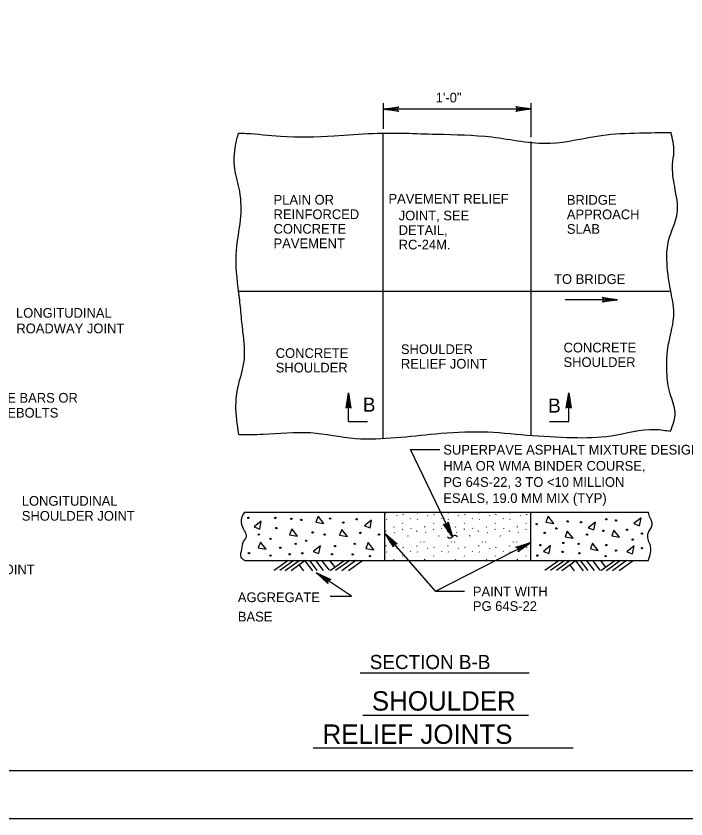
# Model space of a CAD drawing. Extents: x 638216 to 639962, y 297510 to 299292.
# Drawn here: x 638609.5 to 638817, y 297510.2 to 297758.8 of the extents above; entities that cross this region are included whole.
import ezdxf

# ---------------------------------------------------------------- set-up
doc = ezdxf.new("R2010")
doc.units = 0
for name, color, linetype in [('1', 7, 'Continuous'), ('2', 7, 'Continuous'), ('3', 7, 'Continuous'), ('PLT-BNDY', 7, 'Continuous')]:
    doc.layers.add(name, color=color, linetype=linetype)

msp = doc.modelspace()

# ---------------------------------------------------------------- linework, layer by layer
at = {"layer": '1'}
for p, q in [((638744.68, 297597.58), (638731.62, 297624.67)), ((638724.08, 297604.86), (638724.16, 297605.02)), ((638727.38, 297604.23), (638727.45, 297604.12)), ((638729.39, 297604.44), (638729.46, 297604.6)), ((638733.65, 297604.86), (638733.72, 297605.02)), ((638736.94, 297604.23), (638737.01, 297604.12)), ((638738.95, 297604.44), (638739.03, 297604.6)), ((638743.22, 297604.86), (638743.29, 297605.02)), ((638746.51, 297604.23), (638746.58, 297604.12)), ((638748.52, 297604.44), (638748.59, 297604.6)), ((638752.78, 297604.86), (638752.85, 297605.02)), ((638756.07, 297604.23), (638756.15, 297604.12)), ((638758.09, 297604.44), (638758.16, 297604.6)), ((638762.35, 297604.86), (638762.42, 297605.02)), ((638765.64, 297604.23), (638765.71, 297604.12)), ((638767.65, 297604.44), (638767.72, 297604.6)), ((638724.2, 297603.1), (638724.27, 297602.99)), ((638729.15, 297601.82), (638729.22, 297601.71)), ((638731.64, 297603.29), (638731.71, 297603.18)), ((638733.76, 297603.1), (638733.83, 297602.99)), ((638738.72, 297601.82), (638738.79, 297601.71)), ((638741.2, 297603.29), (638741.27, 297603.18)), ((638743.33, 297603.1), (638743.4, 297602.99)), ((638748.28, 297601.82), (638748.35, 297601.71)), ((638750.77, 297603.29), (638750.84, 297603.18)), ((638752.89, 297603.1), (638752.97, 297602.99)), ((638757.85, 297601.82), (638757.92, 297601.71)), ((638760.33, 297603.29), (638760.41, 297603.18)), ((638762.46, 297603.1), (638762.53, 297602.99)), ((638767.41, 297601.82), (638767.49, 297601.71)), ((638723.92, 297599.42), (638723.94, 297599.26)), ((638726.48, 297600.61), (638726.55, 297600.77)), ((638726.74, 297598.95), (638726.81, 297598.84)), ((638729.21, 297599.88), (638729.28, 297600.04)), ((638731.7, 297600.22), (638731.78, 297600.12)), ((638733.48, 297599.42), (638733.5, 297599.26)), ((638736.04, 297600.61), (638736.11, 297600.77)), ((638736.3, 297598.95), (638736.37, 297598.84)), ((638738.77, 297599.88), (638738.85, 297600.04)), ((638741.27, 297600.22), (638741.34, 297600.12)), ((638743.05, 297599.42), (638743.07, 297599.26)), ((638745.61, 297600.61), (638745.68, 297600.77)), ((638745.87, 297598.95), (638745.94, 297598.84)), ((638748.34, 297599.88), (638748.41, 297600.04)), ((638750.84, 297600.22), (638750.91, 297600.12)), ((638752.62, 297599.42), (638752.63, 297599.26)), ((638755.17, 297600.61), (638755.25, 297600.77)), ((638755.44, 297598.95), (638755.51, 297598.84)), ((638757.91, 297599.88), (638757.98, 297600.04)), ((638760.4, 297600.22), (638760.47, 297600.12)), ((638762.18, 297599.42), (638762.2, 297599.26)), ((638764.74, 297600.61), (638764.81, 297600.77)), ((638765, 297598.95), (638765.07, 297598.84)), ((638767.47, 297599.88), (638767.54, 297600.04)), ((638725.15, 297596.07), (638725.22, 297595.96)), ((638726.17, 297596.03), (638726.24, 297595.92)), ((638730.85, 297597.79), (638730.92, 297597.95)), ((638734.71, 297596.07), (638734.78, 297595.96)), ((638735.74, 297596.03), (638735.81, 297595.92)), ((638740.41, 297597.79), (638740.48, 297597.95)), ((638744.28, 297596.07), (638744.35, 297595.96)), ((638745.3, 297596.03), (638745.37, 297595.92)), ((638749.98, 297597.79), (638750.05, 297597.95)), ((638753.84, 297596.07), (638753.92, 297595.96)), ((638754.87, 297596.03), (638754.94, 297595.92)), ((638759.54, 297597.79), (638759.62, 297597.95)), ((638763.41, 297596.07), (638763.48, 297595.96)), ((638764.43, 297596.03), (638764.51, 297595.92)), ((638724.08, 297594.74), (638724.16, 297594.9)), ((638727.38, 297594.11), (638727.45, 297594.01)), ((638729.39, 297594.32), (638729.46, 297594.49)), ((638733.65, 297594.74), (638733.72, 297594.9)), ((638736.94, 297594.11), (638737.01, 297594.01)), ((638738.95, 297594.32), (638739.03, 297594.49)), ((638743.22, 297594.74), (638743.29, 297594.9)), ((638746.51, 297594.11), (638746.58, 297594.01)), ((638748.52, 297594.32), (638748.59, 297594.49)), ((638752.78, 297594.74), (638752.85, 297594.9)), ((638756.07, 297594.11), (638756.15, 297594.01)), ((638758.09, 297594.32), (638758.16, 297594.49)), ((638762.35, 297594.74), (638762.42, 297594.9)), ((638765.64, 297594.11), (638765.71, 297594.01)), ((638767.65, 297594.32), (638767.72, 297594.49)), ((638724.2, 297592.98), (638724.27, 297592.87)), ((638729.15, 297591.7), (638729.22, 297591.59)), ((638731.64, 297593.17), (638731.71, 297593.07)), ((638733.76, 297592.98), (638733.83, 297592.87)), ((638738.72, 297591.7), (638738.79, 297591.59)), ((638741.2, 297593.17), (638741.27, 297593.07)), ((638743.33, 297592.98), (638743.4, 297592.87)), ((638748.28, 297591.7), (638748.35, 297591.59)), ((638750.77, 297593.17), (638750.84, 297593.07)), ((638752.89, 297592.98), (638752.97, 297592.87)), ((638757.85, 297591.7), (638757.92, 297591.59)), ((638760.33, 297593.17), (638760.41, 297593.07)), ((638762.46, 297592.98), (638762.53, 297592.87)), ((638767.41, 297591.7), (638767.49, 297591.59)), ((638726.48, 297590.49), (638726.55, 297590.66)), ((638736.04, 297590.49), (638736.11, 297590.66)), ((638745.61, 297590.49), (638745.68, 297590.66)), ((638755.17, 297590.49), (638755.25, 297590.66)), ((638764.74, 297590.49), (638764.81, 297590.66))]:
    msp.add_line(p, q, dxfattribs=at)
msp.add_lwpolyline([(639041.88, 297525.24), (639041.88, 298089.24), (638255.88, 298089.24), (638255.88, 297525.24), (639041.88, 297525.24), (639041.88, 297551.6), (638841.88, 297551.6), (638841.88, 297616.28), (639041.88, 297616.28), (639041.88, 297645.24), (638841.88, 297645.24), (638841.88, 297525.24), (638920.69, 297525.24), (638920.69, 297551.6), (638920.69, 297525.24), (638997.69, 297525.24), (638997.69, 297551.6), (638997.69, 297539.28), (639041.88, 297539.28)], dxfattribs=at)
msp.add_lwpolyline([(639041.88, 297525.24), (639041.88, 298089.24), (638255.88, 298089.24), (638255.88, 297525.24), (639041.88, 297525.24), (639041.88, 297551.6), (638841.88, 297551.6), (638841.88, 297616.28), (639041.88, 297616.28), (639041.88, 297645.24), (638841.88, 297645.24), (638841.88, 297525.24), (638920.69, 297525.24), (638920.69, 297551.6), (638920.69, 297525.24), (638997.69, 297525.24), (638997.69, 297551.6), (638997.69, 297539.28), (639041.88, 297539.28)], dxfattribs=at)
msp.add_lwpolyline([(639041.88, 297525.24), (639041.88, 298089.24), (638255.88, 298089.24), (638255.88, 297525.24), (639041.88, 297525.24), (639041.88, 297551.6), (638841.88, 297551.6), (638841.88, 297616.28), (639041.88, 297616.28), (639041.88, 297645.24), (638841.88, 297645.24), (638841.88, 297525.24), (638920.69, 297525.24), (638920.69, 297551.6), (638920.69, 297525.24), (638997.69, 297525.24), (638997.69, 297551.6), (638997.69, 297539.28), (639041.88, 297539.28)], dxfattribs=at)
msp.add_spline([(638746.24, 297597.62), (638745.35, 297598.04), (638743.99, 297597.12), (638743.12, 297597.49)], degree=3, dxfattribs=at)
at = {"layer": '2'}
for p, q in [((638723.29, 297723.88), (638723.29, 297731.82)), ((638768.99, 297721.32), (638768.99, 297731.84)), ((638723.85, 297730.05), (638768.99, 297730.05)), ((638723.23, 297628.12), (638723.23, 297722.53)), ((638769.07, 297629.12), (638769.07, 297720.03)), ((638678.21, 297673.67), (638811.9, 297673.67)), ((638779.56, 297671.04), (638792.13, 297671.04)), ((638712.44, 297633.26), (638712.44, 297642.15)), ((638780.66, 297633.26), (638780.66, 297642.15)), ((638712.44, 297633.26), (638718.37, 297633.26)), ((638774.73, 297633.26), (638780.66, 297633.26)), ((638731.62, 297624.67), (638740.76, 297624.67)), ((638680.32, 297605.21), (638805.32, 297605.21)), ((638723.72, 297590.23), (638723.72, 297605.21)), ((638768.92, 297590.23), (638768.92, 297605.21)), ((638739.37, 297580.75), (638723.86, 297598.56)), ((638739.37, 297580.75), (638768.92, 297595.83)), ((638680.32, 297590.21), (638805.32, 297590.21)), ((638693.78, 297590.28), (638689.42, 297587.13)), ((638695.53, 297590.28), (638691.16, 297587.13)), ((638697.15, 297590.2), (638692.78, 297587.05)), ((638699.05, 297590.23), (638694.69, 297587.09)), ((638697.21, 297588.77), (638698.51, 297587.08)), ((638698.93, 297590.11), (638701.26, 297587.09)), ((638700.33, 297590.23), (638702.66, 297587.21)), ((638702.29, 297590.19), (638704.62, 297587.17)), ((638704.09, 297590.28), (638706.42, 297587.25)), ((638706.59, 297590.23), (638708.07, 297588.31)), ((638711.08, 297590.19), (638706.72, 297587.04)), ((638712.83, 297590.26), (638708.46, 297587.11)), ((638714.72, 297590.23), (638710.35, 297587.09)), ((638716.77, 297590.19), (638712.41, 297587.04)), ((638777.66, 297590.26), (638773.3, 297587.11)), ((638779.41, 297590.26), (638775.04, 297587.11)), ((638781.13, 297590.25), (638776.89, 297587.19)), ((638782.93, 297590.21), (638778.57, 297587.07)), ((638781.09, 297588.74), (638782.39, 297587.06)), ((638782.81, 297590.09), (638785.14, 297587.07)), ((638784.21, 297590.21), (638786.54, 297587.19)), ((638786.17, 297590.17), (638788.5, 297587.15)), ((638787.97, 297590.26), (638790.3, 297587.23)), ((638790.47, 297590.21), (638791.95, 297588.29)), ((638794.96, 297590.17), (638790.6, 297587.02)), ((638796.71, 297590.23), (638792.34, 297587.09)), ((638798.6, 297590.21), (638794.23, 297587.07)), ((638800.65, 297590.17), (638796.29, 297587.02)), ((638713.39, 297579.18), (638702.55, 297586.4)), ((638706.79, 297579.18), (638713.39, 297579.18)), ((638739.37, 297580.75), (638748.38, 297580.75)), ((638716.06, 297555.52), (638768.37, 297555.52)), ((638716.87, 297542.37), (638768.21, 297542.37)), ((638701.48, 297532.29), (638782.06, 297532.29))]:
    msp.add_line(p, q, dxfattribs=at)
for points in [[(638727.83, 297729.43), (638727.67, 297729.75), (638723.29, 297729.99), (638727.83, 297729.43), (638728.07, 297729.23), (638723.29, 297729.99), (638727.66, 297730.21), (638727.82, 297730.54), (638723.29, 297729.99), (638728.07, 297730.75), (638727.82, 297730.54)], [(638764.45, 297730.62), (638764.62, 297730.29), (638768.99, 297730.05), (638764.45, 297730.62), (638764.22, 297730.82), (638768.99, 297730.05), (638764.62, 297729.83), (638764.46, 297729.51), (638768.99, 297730.05), (638764.22, 297729.29), (638764.46, 297729.51)], [(638791.2, 297671.55), (638791.37, 297671.22), (638795.74, 297670.98), (638791.2, 297671.55), (638790.97, 297671.75), (638795.74, 297670.98), (638791.38, 297670.77), (638791.22, 297670.44), (638795.74, 297670.98), (638790.97, 297670.22), (638791.22, 297670.44)], [(638711.87, 297637.61), (638712.2, 297637.78), (638712.44, 297642.15), (638711.87, 297637.61), (638711.67, 297637.37), (638712.44, 297642.15), (638712.65, 297637.78), (638712.98, 297637.62), (638712.44, 297642.15), (638713.2, 297637.37), (638712.98, 297637.62)], [(638780.09, 297637.61), (638780.42, 297637.78), (638780.66, 297642.15), (638780.09, 297637.61), (638779.89, 297637.37), (638780.66, 297642.15), (638780.88, 297637.78), (638781.2, 297637.62), (638780.66, 297642.15), (638781.42, 297637.37), (638781.2, 297637.62)], [(638743.2, 297601.91), (638742.98, 297601.62), (638744.68, 297597.58), (638743.2, 297601.91), (638743.28, 297602.21), (638744.68, 297597.58), (638742.57, 297601.41), (638742.21, 297601.42), (638744.68, 297597.58), (638741.91, 297601.54), (638742.21, 297601.42)], [(638726.41, 297594.76), (638726.55, 297595.1), (638723.86, 297598.56), (638726.41, 297594.76), (638726.41, 297594.45), (638723.86, 297598.56), (638726.89, 297595.41), (638727.24, 297595.5), (638723.86, 297598.56), (638727.56, 297595.46), (638727.24, 297595.5)], [(638764.61, 297594.28), (638764.91, 297594.06), (638768.92, 297595.83), (638764.61, 297594.28), (638764.32, 297594.35), (638768.92, 297595.83), (638765.13, 297593.65), (638765.13, 297593.29), (638768.92, 297595.83), (638765.01, 297592.99), (638765.13, 297593.29)], [(638706.01, 297583.41), (638706.05, 297583.77), (638702.55, 297586.4), (638706.01, 297583.41), (638706.09, 297583.11), (638702.55, 297586.4), (638706.3, 297584.16), (638706.62, 297584.34), (638702.55, 297586.4), (638706.94, 297584.39), (638706.62, 297584.34)]]:
    msp.add_lwpolyline(points, dxfattribs=at)
for points in [[(638703.03, 297603.95), (638702.36, 297602.17), (638704.8, 297601.73)], [(638774.26, 297603.95), (638773.59, 297602.17), (638776.03, 297601.73)], [(638800.83, 297601.66), (638802.61, 297600.99), (638803.05, 297603.42)], [(638683.19, 297600.65), (638684.97, 297599.98), (638685.41, 297602.41)], [(638717.37, 297601.02), (638719.16, 297600.35), (638719.6, 297602.78)], [(638786.67, 297600.39), (638788.46, 297599.72), (638788.9, 297602.15)], [(638694.87, 297600.03), (638694.2, 297598.25), (638696.63, 297597.81)], [(638710.34, 297599.87), (638709.67, 297598.08), (638712.11, 297597.64)], [(638780.21, 297599.36), (638779.54, 297597.58), (638781.98, 297597.14)], [(638794.65, 297599.69), (638793.98, 297597.9), (638796.41, 297597.46)], [(638685.18, 297595.95), (638684.51, 297594.17), (638686.95, 297593.72)], [(638701.5, 297593.06), (638703.29, 297592.39), (638703.73, 297594.82)], [(638718.51, 297595.79), (638717.83, 297594), (638720.27, 297593.56)], [(638772.79, 297593.09), (638774.58, 297592.42), (638775.02, 297594.86)], [(638788.03, 297595.61), (638787.36, 297593.82), (638789.79, 297593.38)], [(638798.67, 297592.99), (638800.45, 297592.32), (638800.9, 297594.75)]]:
    msp.add_lwpolyline(points, close=True, dxfattribs=at)
for centre in [(638681.43, 297603.42), (638689.81, 297603.42), (638694.7, 297603.18), (638706.76, 297603.23), (638697.81, 297602.84), (638710.84, 297602.01), (638714.95, 297603.03), (638770.76, 297601.51), (638780.36, 297602.35), (638784.47, 297602.08), (638792.28, 297603.03), (638795.33, 297602.68), (638684.67, 297598.27), (638690.11, 297600.3), (638701.34, 297598.94), (638705.05, 297598.27), (638716.12, 297598.78), (638721.91, 297598.27), (638773.24, 297598.78), (638776.85, 297600.18), (638786.31, 297598.27), (638791.41, 297599.45), (638798.72, 297599.79), (638803.31, 297598.6), (638688.28, 297596.94), (638699.33, 297596.36), (638779, 297595.71), (638800.47, 297596.75), (638691.31, 297594.19), (638696.09, 297595.41), (638708.3, 297594.7), (638714.38, 297595.41), (638771.9, 297595.03), (638783.71, 297595.41), (638792.28, 297595.03), (638795.33, 297593.34), (638803.33, 297594.08), (638681.62, 297592.55), (638688.28, 297591.79), (638694.19, 297592.17), (638698.11, 297592.48), (638707.33, 297592.17), (638713.74, 297592.14), (638719.14, 297591.6), (638770.95, 297591.79), (638778.76, 297592.93), (638783.94, 297592.48), (638792.09, 297591.6)]:
    msp.add_circle(centre, 0.21, dxfattribs=at)
for points in [[(638678.38, 297722.61), (638680.71, 297722.51), (638691.35, 297721.63), (638707.98, 297721.75), (638720.05, 297722.51), (638739.73, 297722.26), (638756.86, 297721.38), (638774.87, 297719.46), (638790.75, 297721.88), (638802.54, 297722.63), (638812.35, 297722.82)], [(638812.18, 297630.26), (638813.6, 297636.1), (638812.09, 297641.81), (638811.06, 297648.53), (638811.58, 297657.3), (638813.22, 297666.94), (638812.18, 297674.01), (638811.06, 297683.57), (638811.58, 297689.28), (638814.23, 297697.66), (638813.47, 297706.03), (638812.84, 297712.88), (638813.22, 297716.83), (638812.35, 297722.82)], [(638678.49, 297629.29), (638677.58, 297638.3), (638678.23, 297644.01), (638680.12, 297651.88), (638679.75, 297661.02), (638679.12, 297667.23), (638678.49, 297673.04), (638677.73, 297686.28), (638678.99, 297695.68), (638678.74, 297704.56), (638677.21, 297711.53), (638677.46, 297718.78), (638678.38, 297722.61)], [(638678.49, 297629.29), (638686.04, 297629.35), (638700.63, 297629.86), (638714.59, 297628.07), (638727.15, 297628.32), (638739.35, 297629.48), (638753.94, 297630.11), (638767.65, 297629.1), (638781.87, 297628.32), (638793.79, 297628.85), (638807.5, 297630.86), (638812.18, 297630.26)], [(638680.32, 297590.21), (638679.17, 297591.33), (638679.44, 297593.79), (638679.94, 297596.1), (638680.85, 297597.84), (638680.28, 297599.4), (638679.32, 297602.13), (638679.38, 297603.3), (638680.32, 297605.21)], [(638805.32, 297590.21), (638805.98, 297592.66), (638805.84, 297595.18), (638805.21, 297596.86), (638805.35, 297598.96), (638805.98, 297600.07), (638806.47, 297601.27), (638806.26, 297602.59), (638805.84, 297603.43), (638805.32, 297605.21)]]:
    msp.add_spline(points, degree=3, dxfattribs=at)
at = {"layer": 'PLT-BNDY'}
msp.add_lwpolyline([(638215.88, 298104.24), (639056.88, 298104.24), (639056.88, 297510.24), (638215.88, 297510.24)], close=True, dxfattribs=at)

# ---------------------------------------------------------------- texts
at = {"layer": '3'}
for s, height, p in [('1\'-0"', 3, (638739.45, 297732.07)), ('PLAIN OR', 3, (638689.23, 297700.45)), ('PAVEMENT RELIEF', 3, (638724.82, 297700.77)), ('BRIDGE', 3, (638780.07, 297700.41)), ('REINFORCED', 3, (638689.23, 297695.95)), ('JOINT, SEE', 3, (638727.99, 297695.56)), ('APPROACH', 3, (638780.07, 297695.91)), ('CONCRETE', 3, (638689.23, 297691.45)), ('DETAIL,', 3, (638727.99, 297691.06)), ('SLAB', 3, (638780.07, 297691.41)), ('PAVEMENT', 3, (638689.23, 297686.95)), ('RC-24M.', 3, (638727.99, 297686.56)), ('TO BRIDGE', 3, (638776.12, 297675.89)), ('LONGITUDINAL ', 3, (638609.45, 297665.42)), ('ROADWAY JOINT', 3, (638609.57, 297660.61)), ('CONCRETE', 3, (638689.9, 297652.97)), ('SHOULDER ', 3, (638728.67, 297654.17)), ('CONCRETE', 3, (638779.04, 297654.68)), ('SHOULDER', 3, (638779.04, 297650.18)), ('SHOULDER', 3, (638689.9, 297648.47)), ('RELIEF JOINT', 3, (638728.67, 297649.67)), ('TIE BARS OR', 3, (638603.19, 297639.13)), ('B', 4.37, (638716.9, 297636.34)), ('B', 4.37, (638774.28, 297636.04)), ('TIEBOLTS', 3, (638603.19, 297634.5)), ('SUPERPAVE ASPHALT MIXTURE DESIGN,', 3, (638741.81, 297623.06)), ('HMA OR WMA BINDER COURSE, ', 3, (638741.81, 297618.06)), ('PG 64S-22, 3 TO <10 MILLION ', 3, (638741.81, 297613.06)), ('ESALS, 19.0 MM MIX (TYP)', 3, (638741.81, 297608.06)), ('LONGITUDINAL', 3, (638611.25, 297607.21)), ('SHOULDER JOINT', 3, (638611.25, 297602.58)), ('TRANSVERSE SHOULDER JOINT', 3, (638551.93, 297586.01)), ('PAINT WITH', 3, (638750.97, 297579.14)), ('AGGREGATE', 3, (638678.17, 297577.37)), ('PG 64S-22', 3, (638750.97, 297574.64)), ('BASE', 3, (638678.17, 297571.37)), ('SECTION B-B', 4.375, (638719.02, 297556.64)), ('SHOULDER', 6, (638719.66, 297543.78)), ('RELIEF JOINTS', 6, (638704.39, 297533.49))]:
    msp.add_text(s, height=height, dxfattribs=at).set_placement(p)

doc.saveas('drawing.dxf')
